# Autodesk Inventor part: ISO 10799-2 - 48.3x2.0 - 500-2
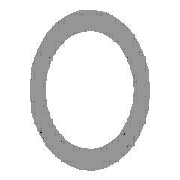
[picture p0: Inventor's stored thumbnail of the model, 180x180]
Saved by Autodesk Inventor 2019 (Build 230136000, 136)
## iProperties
IsCustomPart: 1
Created: 2018-07
Part Number: ISO 10799-2 - 48.3x2.0 - 500-2
Material: Acier, doux
Description: Aciers de construction - Coupes creuses profilées formées à froid, soudées
Document SubType Name: Modeling
Standard: ISO
Designer: Fabian Perrée
Standard Revision: First edition 2011-09-15
Standards Organization: ISO
Language: fr-FR
Size Designation: 48.3x2.0
Categories: <MemberInstance><Categories><Category DisplayName="Profilés" InternalName="089c4875-fa83-4c05-b084-43b9cc11f5ed" Mnemonic="GRDR"><CategoryParameter DisplayName=
Stock Number: 48.3x2.0
Density: 7.85 g/cm^3
Appearance: Semi-poli
Mass: 1103.72 g
Surface Area: 1414.8 cm^2
Volume: 140.601 cm^3
_CCFamilyMember: 14
_CCFamilyDisplayName: ISO 10799-2 (Profils creux circulaires - Formés à froid) - Aciers de construction - Coupes creuses profilées formées à froid, soudées
_FrameMemberDoc: Frame Member File
_Version: 15.0.0
_GetPNFromCC: 1
G_L: 500,000 mm
G_W: 48,300 mm
G_H: 48,300 mm
+827D7E4F-AC72-4F13-A4D1-31AC1668D8DC+DETAILDECOUPE1: Grugeage
Author: Fabian Perrée
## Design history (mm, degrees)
node "Plan de départ"
node "Plan de fin"
sketch "Esquisse"
  geometry: C1 r 22.15 at (0, 0); C2 r 24.15 at (0, 0); 2 further points
  constraints: 3 coincident, 2 centre point
  dimensions: "d0" = 48.3 diameter of C2 (= G_H); "d1" = 2 radial gap between concentric circles of C2 C1 (= G_T)
extrude "Corps" new body sketch "Esquisse" stored distance "d2" = 500 (= G_L); taper "d3" = 0 deg
node "Driven Length"
  sketch "Sketch3"
    geometry: L1 (0, 0)-(10, 0) reference
    constraints: 2 end point, 1 horizontal
  workplane "Work Plane3"
  sketch "Sketch4"
    geometry: L1 (-2, 0)-(12, 0) reference; L2 (-2, 500)-(12, 500) reference
    dimensions: "d7" = 500 distance between parallel lines of L1 L2 (derived)
body "Solid1"
feature "Sculpter1"
feature "Combiner1"
body "Srf14"
body "Srf15"
node "Solide6"
feature "Surface1"
body "Srf13"
feature "Carreau délimité9" dims "d24" = 5, "d25" = 0
feature "Carreau délimité10" dims "d26" = 5, "d27" = 0
other parameters: "G_H" = 48.3 [user parameter; used in 1 equation term], "G_T" = 2 [user parameter; used in 1 equation term], "G_L" = 500 (= d7) [user parameter; used in 1 equation term], "G_OFFSET_START" = 0 [user parameter; used in 1 equation term], "G_OFFSET_END" = 0 [user parameter; used in 1 equation term], "d4" = 0 (computed from G_OFFSET_START), "d5" = 500 (= G_OFFSET_END + B_L), "B_L" = 500 [user parameter; used in 1 equation term], "d6" = 90 deg, "MAS" = 0.228 [user parameter]
